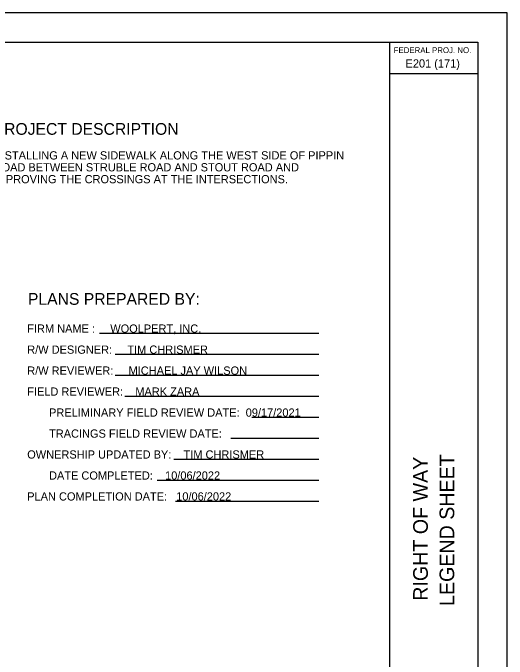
# Model space of a CAD drawing. Extents: x 0 to 34, y 0 to 22.
# Drawn here: x 25.58 to 34, y 11 to 22 of the extents above; entities that cross this region are included whole.
import ezdxf

# ---------------------------------------------------------------- set-up
doc = ezdxf.new("R2010")
doc.units = 0
for name, color, linetype in [('SH_Border', 7, 'Continuous'), ('SH_Cut_Line', 7, 'Continuous'), ('SH_Data', 7, 'Continuous'), ('SH_Text', 7, 'Continuous')]:
    doc.layers.add(name, color=color, linetype=linetype)

msp = doc.modelspace()

# ---------------------------------------------------------------- linework, layer by layer
at = {"layer": 'SH_Border'}
msp.add_line((32, 0.5), (32, 21.5), dxfattribs=at)
msp.add_lwpolyline([(1.5, 21.5), (33.5, 21.5), (33.5, 0.5), (1.5, 0.5)], close=True, dxfattribs=at)
at = {"layer": 'SH_Cut_Line'}
msp.add_lwpolyline([(0, 0), (34, 0), (34, 22), (0, 22)], close=True, dxfattribs=at)
at = {"layer": 'SH_Data'}
msp.add_line((32, 20.966), (33.5, 20.966), dxfattribs=at)
at = {"layer": 'SH_Text'}
for p, q in [((27.058, 16.546), (30.795, 16.546)), ((27.322, 16.189), (30.795, 16.189)), ((27.322, 15.831), (30.795, 15.831)), ((27.486, 15.474), (30.795, 15.474)), ((29.65, 15.117), (30.795, 15.117)), ((29.292, 14.76), (30.795, 14.76)), ((28.322, 14.403), (30.795, 14.403)), ((28.037, 14.045), (30.795, 14.045)), ((28.352, 13.689), (30.795, 13.689))]:
    msp.add_line(p, q, dxfattribs=at)

# ---------------------------------------------------------------- texts
at = {"layer": 'SH_Data'}
for s, height, p in [('FEDERAL PROJ. NO.', 0.1, (32.068, 21.316)), ('E201 (171)', 0.14, (32.27, 21.07)), ('PROJECT DESCRIPTION', 0.2, (25.254, 19.925)), ('INSTALLING A NEW SIDEWALK ALONG THE WEST SIDE OF PIPPIN ', 0.14, (25.254, 19.505)), ('ROAD BETWEEN STRUBLE ROAD AND STOUT ROAD AND ', 0.14, (25.254, 19.302)), ('IMPROVING THE CROSSINGS AT THE INTERSECTIONS.', 0.14, (25.254, 19.1))]:
    msp.add_text(s, height=height, dxfattribs=at).set_placement(p)
for s, p in [('RIGHT OF WAY', (32.65, 11.993)), ('LEGEND SHEET', (33.1, 11.904))]:
    msp.add_text(s, height=0.25, rotation=90, dxfattribs=at).set_placement(p)
at = {"layer": 'SH_Text'}
for s, height, p in [('PLANS PREPARED BY:', 0.2, (25.838, 17.031)), ('FIRM NAME :     WOOLPERT, INC.', 0.14, (25.826, 16.556)), ('R/W DESIGNER:     TIM CHRISMER', 0.14, (25.826, 16.198)), ('R/W REVIEWER:     MICHAEL JAY WILSON', 0.14, (25.826, 15.841)), ('FIELD REVIEWER:    MARK ZARA', 0.14, (25.826, 15.484)), ('PRELIMINARY FIELD REVIEW DATE:  09/17/2021', 0.14, (26.198, 15.127)), ('TRACINGS FIELD REVIEW DATE:', 0.14, (26.198, 14.769)), ('OWNERSHIP UPDATED BY:    TIM CHRISMER', 0.14, (25.826, 14.413)), ('DATE COMPLETED:    10/06/2022', 0.14, (26.198, 14.055)), ('PLAN COMPLETION DATE:   10/06/2022', 0.14, (25.826, 13.699))]:
    msp.add_text(s, height=height, dxfattribs=at).set_placement(p)

doc.saveas('drawing.dxf')
